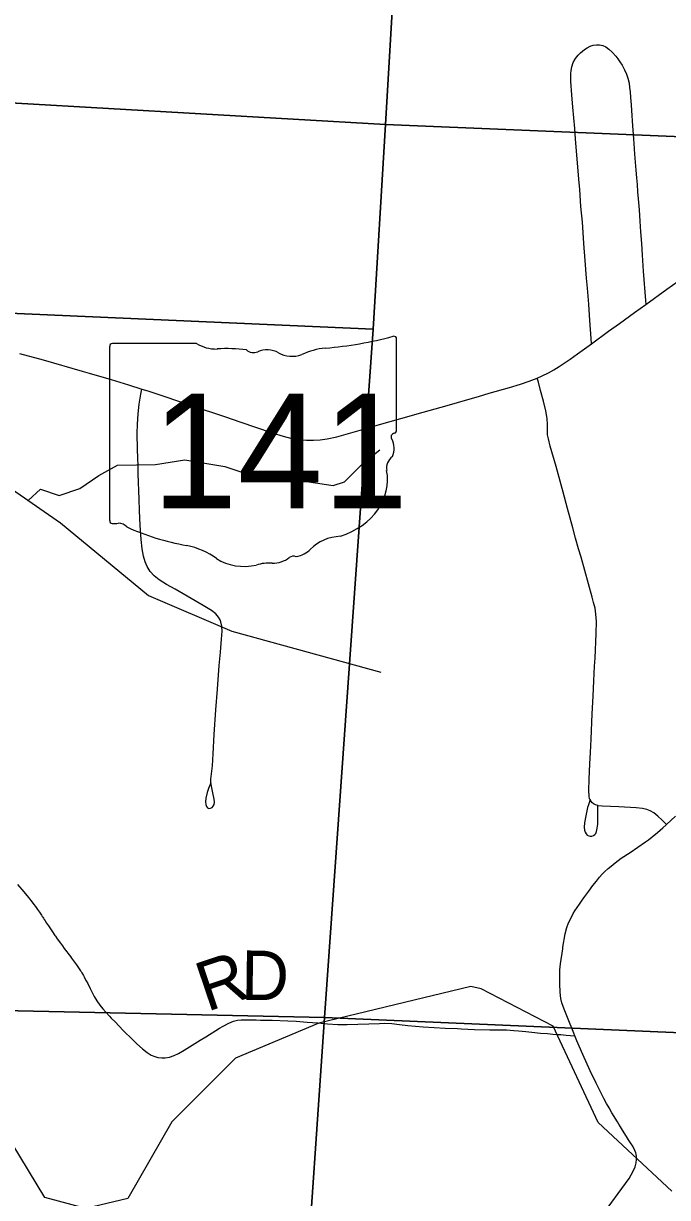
# Model space of a CAD drawing. Extents: x 0 to 34, y 0 to 22.
# Drawn here: x 26.149 to 26.889, y 17.797 to 19.146 of the extents above; entities that cross this region are included whole.
import ezdxf

# ---------------------------------------------------------------- set-up
doc = ezdxf.new("R2010")
doc.units = 0
for name, color, linetype in [('GM_X_County_Road', 7, 'Continuous'), ('GM_X_Minor_River', 7, 'Continuous'), ('GM_X_Section', 7, 'Continuous'), ('GM_X_State_Location', 7, 'Continuous'), ('GM_X_State_Route', 7, 'Continuous'), ('GM_X_State_Shield', 7, 'Continuous'), ('GM_X_Township_Road', 7, 'Continuous'), ('GM_X_Township_Road_Text', 7, 'Continuous')]:
    doc.layers.add(name, color=color, linetype=linetype)

msp = doc.modelspace()

# ---------------------------------------------------------------- linework, layer by layer
at = {"layer": 'GM_X_County_Road'}
for points in [[(26.7868, 18.542), (26.7833, 18.5545), (26.78, 18.5663), (26.774, 18.5884), (26.7689, 18.6073), (26.7643, 18.624), (26.7609, 18.6366), (26.7543, 18.6599), (26.7521, 18.6684), (26.7512, 18.6733), (26.7509, 18.6771), (26.751, 18.6809), (26.7512, 18.6851), (26.7506, 18.6918), (26.749, 18.7008), (26.7464, 18.7117), (26.7432, 18.7239), (26.7406, 18.7338), (26.7393, 18.7383)], [(26.8879, 18.2254), (26.8828, 18.2303), (26.8779, 18.235), (26.8731, 18.2386), (26.8689, 18.241), (26.865, 18.2426), (26.8603, 18.2438), (26.853, 18.2446), (26.8331, 18.2456), (26.8139, 18.2463), (26.8094, 18.2468), (26.8087, 18.2471), (26.8063, 18.2478), (26.804, 18.2491), (26.8019, 18.2508), (26.8007, 18.2524), (26.7999, 18.2541), (26.7995, 18.2549), (26.7988, 18.2581), (26.7985, 18.2644), (26.799, 18.2775), (26.7996, 18.2949), (26.8003, 18.3079), (26.8011, 18.3234), (26.8024, 18.3525), (26.8034, 18.373), (26.8043, 18.3904), (26.8052, 18.4071), (26.8057, 18.4164), (26.8071, 18.4449), (26.8072, 18.4585), (26.8067, 18.4671), (26.8057, 18.4738), (26.804, 18.4805), (26.8025, 18.4864), (26.7896, 18.5324), (26.7868, 18.542)], [(26.7688, 18.0844), (26.7715, 18.0996), (26.7733, 18.107), (26.7752, 18.1123), (26.7786, 18.119), (26.7806, 18.1229), (26.7825, 18.126), (26.785, 18.1299), (26.7877, 18.1337), (26.79, 18.1371), (26.7929, 18.1412), (26.7985, 18.1487), (26.8033, 18.1553), (26.8072, 18.1604), (26.8108, 18.1647), (26.814, 18.1683), (26.8166, 18.171), (26.8207, 18.1749), (26.8241, 18.1776), (26.8288, 18.1814), (26.8358, 18.1865), (26.8461, 18.1932), (26.8636, 18.2053), (26.867, 18.2078), (26.8714, 18.2113), (26.8775, 18.2163), (26.8836, 18.2215), (26.8873, 18.2248), (26.8879, 18.2254), (26.8982, 18.2348)], [(26.8175, 17.7816), (26.8321, 17.8013), (26.8449, 17.8185), (26.8496, 17.8269), (26.8519, 17.8321), (26.8529, 17.8364), (26.8533, 17.8404), (26.8533, 17.8438), (26.8529, 17.8464), (26.8524, 17.8479), (26.8512, 17.8509), (26.8489, 17.8557), (26.8464, 17.8595), (26.844, 17.863), (26.8417, 17.8668), (26.8372, 17.8741), (26.8359, 17.8762), (26.835, 17.8778), (26.833, 17.881), (26.8314, 17.8836), (26.825, 17.8942), (26.8218, 17.8996), (26.819, 17.9046), (26.8158, 17.9106), (26.8068, 17.9283), (26.8002, 17.9424), (26.7916, 17.961), (26.7847, 17.9769), (26.7824, 17.9826), (26.7812, 17.9856), (26.7741, 18.0035), (26.7702, 18.0133), (26.7676, 18.0204), (26.7665, 18.0253), (26.7656, 18.0328), (26.7653, 18.0422), (26.7654, 18.0584), (26.766, 18.0652), (26.7685, 18.0825), (26.7688, 18.0844)]]:
    msp.add_lwpolyline(points, dxfattribs=at)
at = {"layer": 'GM_X_Minor_River'}
for points in [[(25.3826, 18.667), (25.4443, 18.6827), (25.4342, 18.7597), (25.473, 18.782), (25.5116, 18.7623), (25.564, 18.7848), (25.6067, 18.8573), (25.6367, 18.8632), (25.6511, 18.8588), (25.8282, 18.8152), (25.9172, 18.7762), (26.0147, 18.6947), (26.1917, 18.5718), (26.293, 18.4884), (26.3885, 18.4475), (26.5595, 18.4005)], [(26.1545, 18.5978), (26.1687, 18.6106), (26.1903, 18.6034), (26.2138, 18.6114), (26.2358, 18.6263), (26.2574, 18.6381), (26.301, 18.6389), (26.3344, 18.6443), (26.3806, 18.6367), (26.4034, 18.6291), (26.4337, 18.6257), (26.505, 18.6148), (26.5178, 18.619), (26.5406, 18.6418), (26.5584, 18.6559)], [(26.8939, 17.8041), (26.8093, 17.8831), (26.7577, 17.9938), (26.6748, 18.0364), (26.663, 18.0393), (26.4885, 17.9971), (26.3926, 17.9568), (26.3196, 17.8836), (26.2691, 17.7955), (26.221, 17.7841), (26.1738, 17.7969), (26.1172, 17.8898)]]:
    msp.add_lwpolyline(points, dxfattribs=at)
at = {"layer": 'GM_X_Section'}
for points in [[(27.6689, 20.0112), (27.6061, 18.9865), (26.5652, 19.0298), (26.5757, 19.2125), (26.6008, 19.6356), (26.6253, 20.056)], [(25.5164, 19.2759), (26.5757, 19.2125), (26.5652, 19.0298), (25.5041, 19.0909)], [(25.5038, 19.0874), (25.5041, 19.0909), (26.5652, 19.0298), (26.551, 18.7947), (25.9675, 18.82), (25.4882, 18.8408)], [(26.5652, 19.0298), (27.6061, 18.9865), (27.5941, 18.7705), (27.5794, 18.5214), (27.5606, 18.2043), (27.546, 17.9583), (26.4949, 18.0036), (26.551, 18.7947)], [(26.551, 18.7947), (26.4949, 18.0036), (25.9143, 18.0162), (25.9675, 18.82)], [(25.4369, 18.0387), (25.9143, 18.0162), (26.4949, 18.0036), (26.4248, 16.9831), (25.8848, 17.0085), (25.3722, 17.0086), (25.3999, 17.4262), (25.4267, 17.8394)], [(26.4949, 18.0036), (27.546, 17.9583), (27.5355, 17.7931), (27.4974, 17.1618), (27.484, 16.9363), (26.4248, 16.9831)]]:
    msp.add_lwpolyline(points, close=True, dxfattribs=at)
at = {"layer": 'GM_X_State_Route'}
msp.add_lwpolyline([(26.1448, 18.7666), (26.1717, 18.7592), (26.2165, 18.7464), (26.2248, 18.744), (26.2498, 18.7365), (26.27, 18.7304), (26.285, 18.7257), (26.2919, 18.7235), (26.3115, 18.717), (26.3407, 18.7072), (26.3813, 18.6937), (26.3977, 18.688), (26.4348, 18.6754), (26.4473, 18.6715), (26.4576, 18.669), (26.4663, 18.6675), (26.4744, 18.6668), (26.4825, 18.6668), (26.4901, 18.6673), (26.4981, 18.6685), (26.5091, 18.671), (26.5414, 18.68), (26.5581, 18.6849), (26.5826, 18.6918), (26.6083, 18.6993), (26.6358, 18.7069), (26.6596, 18.7139), (26.6719, 18.7173), (26.6841, 18.7209), (26.7076, 18.7276), (26.7199, 18.7314), (26.7302, 18.7349), (26.7393, 18.7383), (26.745, 18.7408), (26.7523, 18.7444), (26.7584, 18.7479), (26.7645, 18.7517), (26.777, 18.7601), (26.7856, 18.7662), (26.8017, 18.7778), (26.8213, 18.7921), (26.8339, 18.8012), (26.851, 18.8135), (26.864, 18.8228), (26.8882, 18.8404), (26.9076, 18.8541)], dxfattribs=at)
at = {"layer": 'GM_X_State_Shield'}
for p, q in [((26.5778, 18.6784), (26.5778, 18.7831)), ((26.2482, 18.7747), (26.2482, 18.5745)), ((26.348, 18.7781), (26.2515, 18.7781)), ((26.5778, 18.6784), (26.5778, 18.6784))]:
    msp.add_line(p, q, dxfattribs=at)
for centre, major_axis, start_param, end_param in [((26.4604, 19.0509), (0.3495, 0), 4.814394, 5.042369), ((26.5742, 18.7835), (0.00367, 0), 6.141152, 7.989035), ((26.252, 18.7751), (0.00382, 0), 1.712693, 3.28349), ((26.371, 18.8013), (0.037, 0), 4.042523, 4.731795), ((26.3833, 18.6658), (0.133, 0), 1.404758, 1.657858), ((26.4135, 18.7761), (0.0107, 0), 3.836095, 5.185415), ((26.4291, 18.753), (0.0222, 0), 0.950623, 2.079405), ((26.4578, 18.7847), (0.0267, 0), 4.081561, 5.145723), ((26.505, 18.717), (0.0703, 0), 1.699011, 2.107814), ((26.577, 18.6707), (0.00568, 0), 1.883978, 3.671073), ((26.5739, 18.678), (0.00393, 0), 5.05454, 6.418171), ((26.5409, 18.6575), (0.0341, 0), 5.934695, 6.695948), ((26.591, 18.6346), (0.0248, 0), 2.387724, 3.262537), ((26.48, 18.6213), (0.0874, 0), 5.101752, 6.440018), ((26.2521, 18.5741), (0.00385, 0), 3.00124, 4.508301), ((26.2526, 18.5946), (0.0294, 0), 4.665946, 4.897461), ((26.2587, 18.563), (0.0106, 0), 0.519207, 1.627899), ((26.3925, 18.7428), (0.2524, 0), 4.195997, 4.488961), ((26.5169, 18.5184), (0.0479, 0), 1.647645, 2.488434), ((26.3172, 18.4846), (0.079, 0), 0.823519, 1.323587), ((26.4562, 18.5552), (0.0282, 0), 4.937069, 5.64225), ((26.4026, 18.562), (0.0501, 0), 4.026481, 4.996735), ((26.4316, 18.4928), (0.0412, 0), 1.495662, 1.94098), ((26.4353, 18.547), (0.0267, 0), 4.691044, 5.507374), ((26.4594, 18.5276), (0.00752, 0), 1.147584, 2.315152)]:
    msp.add_ellipse(centre, major_axis=major_axis, ratio=0.8, start_param=start_param, end_param=end_param, dxfattribs=at)
at = {"layer": 'GM_X_Township_Road'}
for points in [[(26.8017, 18.7778), (26.8012, 18.7838), (26.7997, 18.8044), (26.7984, 18.8232), (26.7969, 18.8415), (26.7959, 18.853), (26.7944, 18.8736), (26.7929, 18.8931), (26.792, 18.9056), (26.7911, 18.9174), (26.7894, 18.9353), (26.7881, 18.9552), (26.7871, 18.9667), (26.7831, 19.0134), (26.7823, 19.0251), (26.7813, 19.0374), (26.7803, 19.0497), (26.7791, 19.0639), (26.778, 19.0792), (26.7778, 19.0855), (26.7778, 19.088), (26.7781, 19.0918), (26.7789, 19.0961), (26.7807, 19.1009), (26.7833, 19.1054), (26.7864, 19.1093), (26.7891, 19.112), (26.7935, 19.1157), (26.7966, 19.1178), (26.8, 19.1196), (26.8036, 19.1209), (26.8075, 19.1214), (26.8107, 19.1213), (26.8145, 19.1204), (26.818, 19.1188), (26.8217, 19.1162), (26.8254, 19.1128), (26.8295, 19.1081), (26.8317, 19.1051), (26.8343, 19.1016), (26.8367, 19.098), (26.8397, 19.0926), (26.8419, 19.0875), (26.8434, 19.0828), (26.8447, 19.0773), (26.8453, 19.0724), (26.8459, 19.0673), (26.8464, 19.0608), (26.8471, 19.0522), (26.8476, 19.0456), (26.8487, 19.0283), (26.8498, 19.0134), (26.8503, 19.0079), (26.8511, 18.9955), (26.8524, 18.9773), (26.8532, 18.9683), (26.854, 18.9607), (26.8546, 18.9525), (26.8553, 18.9441), (26.8562, 18.9317), (26.8571, 18.9188), (26.858, 18.9065), (26.859, 18.893), (26.8599, 18.8795), (26.8611, 18.8612), (26.8637, 18.8274), (26.864, 18.8228)], [(26.2802, 18.6559), (26.2801, 18.6568), (26.2798, 18.6748), (26.28, 18.6853), (26.2809, 18.6971), (26.2822, 18.7082), (26.2839, 18.7199), (26.285, 18.7257)], [(26.3646, 18.2733), (26.3619, 18.2666), (26.3603, 18.2622), (26.3587, 18.2557), (26.3583, 18.2513), (26.3586, 18.2483), (26.3594, 18.2459), (26.3605, 18.2445), (26.362, 18.2436), (26.3639, 18.244), (26.3659, 18.2448), (26.3671, 18.2463), (26.3681, 18.2485), (26.3685, 18.251), (26.3683, 18.2546), (26.3668, 18.2618), (26.3646, 18.2733), (26.3646, 18.2776), (26.3662, 18.2929), (26.3672, 18.3065), (26.3684, 18.3288), (26.3703, 18.3573), (26.3721, 18.3808), (26.374, 18.4081), (26.3754, 18.4232), (26.3765, 18.4384), (26.3773, 18.4477), (26.3771, 18.4533), (26.376, 18.4581), (26.375, 18.4604), (26.3732, 18.4636), (26.37, 18.4673), (26.3651, 18.4711), (26.3555, 18.477), (26.3233, 18.4957), (26.3136, 18.5013), (26.3051, 18.5065), (26.2992, 18.511), (26.2947, 18.5162), (26.2912, 18.522), (26.2891, 18.5272), (26.2872, 18.5337), (26.2855, 18.5423), (26.2843, 18.5527), (26.2833, 18.5694), (26.2829, 18.5775), (26.2825, 18.5862), (26.282, 18.5992), (26.2811, 18.6283), (26.2808, 18.637), (26.2805, 18.6469), (26.2802, 18.6559)], [(26.7999, 18.2541), (26.798, 18.248), (26.7969, 18.2448), (26.7961, 18.2411), (26.7951, 18.2352), (26.7937, 18.2271), (26.7933, 18.2221), (26.7935, 18.219), (26.7942, 18.2167), (26.7955, 18.2145), (26.7968, 18.2132), (26.7984, 18.2123), (26.8002, 18.2119), (26.8021, 18.212), (26.8038, 18.2126), (26.8053, 18.2138), (26.8064, 18.2152), (26.8074, 18.2175), (26.8083, 18.221), (26.8089, 18.2259), (26.809, 18.2321), (26.8087, 18.2372), (26.8087, 18.2407), (26.8087, 18.2471)], [(26.1424, 18.1564), (26.1495, 18.1479), (26.155, 18.1413), (26.1562, 18.1399), (26.1581, 18.1375), (26.1589, 18.1365), (26.1604, 18.1346), (26.1611, 18.1336), (26.163, 18.1311), (26.1654, 18.1277), (26.1675, 18.1247), (26.1692, 18.1223), (26.1699, 18.1213), (26.1708, 18.1198), (26.1715, 18.1188), (26.1721, 18.1178), (26.1731, 18.1163), (26.1741, 18.1147), (26.1758, 18.1121), (26.1778, 18.1091), (26.1825, 18.1019), (26.1852, 18.0979), (26.1859, 18.0969), (26.188, 18.0939), (26.1916, 18.0889), (26.1939, 18.0859), (26.1961, 18.083), (26.2031, 18.0736), (26.2045, 18.0716), (26.2067, 18.0686), (26.21, 18.0642), (26.2116, 18.0618), (26.2123, 18.0608), (26.2146, 18.0574), (26.2153, 18.0563), (26.2162, 18.0548), (26.2181, 18.0517), (26.2189, 18.0503), (26.2198, 18.0485), (26.2213, 18.0458), (26.223, 18.0425), (26.2259, 18.037), (26.227, 18.0348), (26.2286, 18.0315), (26.2306, 18.0277), (26.2334, 18.0229), (26.237, 18.0179), (26.2405, 18.0135), (26.2438, 18.0098), (26.2479, 18.0052), (26.2501, 18.0029), (26.2544, 17.9985), (26.2639, 17.9887), (26.2749, 17.9778), (26.2793, 17.9735), (26.2858, 17.9676), (26.2912, 17.9633), (26.296, 17.9604), (26.3001, 17.9586), (26.3037, 17.9576), (26.3081, 17.9571), (26.3119, 17.9573), (26.3169, 17.9581), (26.3222, 17.96), (26.3273, 17.9624), (26.3337, 17.9662), (26.3369, 17.9681), (26.3523, 17.9775), (26.3585, 17.9815), (26.3701, 17.9886), (26.3743, 17.9912), (26.3786, 17.9937), (26.3851, 17.9972), (26.3903, 17.9992), (26.395, 18.0004), (26.3991, 18.0008), (26.407, 18.0009), (26.412, 18.0008), (26.4163, 18.0008), (26.4213, 18.0007), (26.4348, 18.0005), (26.4528, 17.9997), (26.4626, 17.9992), (26.475, 17.9984), (26.4874, 17.9974), (26.4985, 17.9964), (26.5103, 17.9957), (26.5209, 17.9957), (26.5581, 17.9968), (26.5637, 17.9969), (26.5723, 17.9965), (26.581, 17.9956), (26.5908, 17.9944), (26.6081, 17.9929), (26.6211, 17.9921), (26.6335, 17.9913), (26.6478, 17.9908), (26.652, 17.9906), (26.6673, 17.9897), (26.6847, 17.9893), (26.6891, 17.9895), (26.694, 17.9893), (26.7002, 17.9894), (26.7038, 17.9893), (26.7081, 17.989), (26.7123, 17.9886), (26.7176, 17.9883), (26.7221, 17.9879), (26.7263, 17.9874), (26.733, 17.9867), (26.7429, 17.9857), (26.751, 17.9851), (26.7571, 17.9846), (26.7615, 17.9842), (26.7662, 17.9839), (26.7726, 17.9834), (26.7824, 17.9826)]]:
    msp.add_lwpolyline(points, dxfattribs=at)

# ---------------------------------------------------------------- texts
at = {"layer": 'GM_X_State_Location'}
for s in ['r', 's']:
    msp.add_text(s, height=0.000189, dxfattribs=at).set_placement((26.4093, 18.6613))
msp.add_text('141', height=0.000189, rotation=0, dxfattribs=at).set_placement((26.3425, 18.6475))
at = {"layer": 'GM_X_State_Shield'}
msp.add_text('141', height=0.13184, dxfattribs=at).set_placement((26.2968, 18.5887))
at = {"layer": 'GM_X_Township_Road_Text'}
for s, rotation, p in [('D', 359.3188, (26.399, 18.0239)), ('R', 18.7052, (26.3598, 18.0098))]:
    msp.add_text(s, height=0.0568, rotation=rotation, dxfattribs=at).set_placement(p)

doc.saveas('drawing.dxf')
